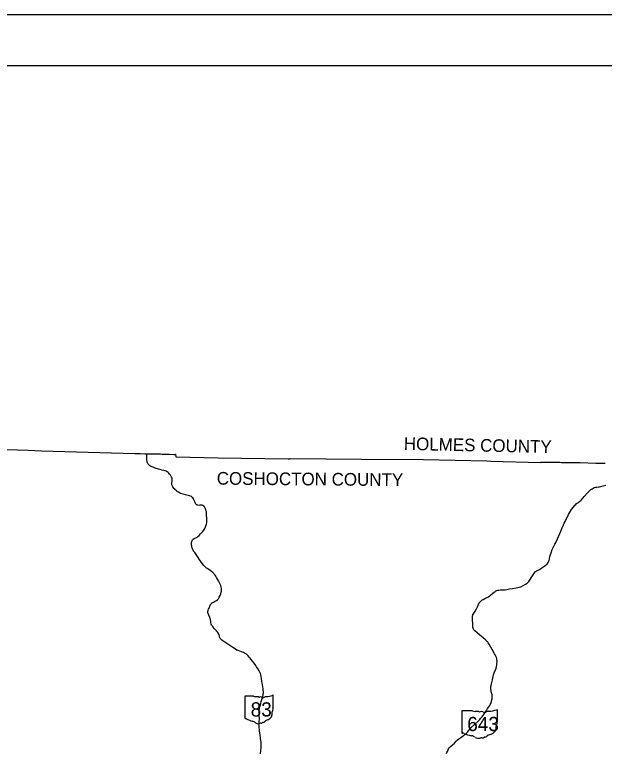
# Model space of a CAD drawing. Extents: x 1913970 to 2276415, y 78841 to 927181.
# Drawn here: x 2124487 to 2170995, y 868928 to 927181 of the extents above; entities that cross this region are included whole.
import ezdxf

# ---------------------------------------------------------------- set-up
doc = ezdxf.new("R2010")
doc.units = 0
for name, color, linetype in [('GM_X_County', 7, 'Continuous'), ('GM_X_County_Text', 7, 'Continuous'), ('GM_X_State_Location', 7, 'Continuous'), ('GM_X_State_Route', 7, 'Continuous'), ('GM_X_State_Shield', 7, 'Continuous'), ('SH_Border', 7, 'Continuous'), ('SH_Cut_Line', 7, 'Continuous')]:
    doc.layers.add(name, color=color, linetype=linetype)

msp = doc.modelspace()

# ---------------------------------------------------------------- linework, layer by layer
at = {"layer": 'GM_X_County'}
msp.add_lwpolyline([(2122132, 892938), (2125547, 892838), (2126585, 892786), (2133951, 892571), (2133956, 892572), (2133965, 892574), (2133971, 892575), (2133978, 892576), (2133984, 892576), (2133992, 892577), (2134003, 892576), (2134090, 892576), (2134158, 892574), (2134373, 892570), (2134751, 892558), (2134916, 892555), (2134951, 892554), (2135202, 892549), (2135323, 892546), (2135463, 892544), (2135510, 892543), (2135606, 892542), (2135654, 892541), (2135717, 892540), (2135760, 892539), (2135871, 892537), (2135937, 892535), (2135985, 892533), (2136113, 892530), (2136193, 892528), (2136275, 892528), (2136373, 892525), (2136668, 892518), (2137044, 892505), (2137101, 892504), (2137123, 892504), (2137135, 892506), (2137144, 892509), (2137152, 892512), (2137161, 892516), (2137167, 892519), (2137174, 892523), (2137184, 892297), (2140547, 892239), (2146047, 892160), (2146063, 892162), (2146077, 892162), (2146095, 892162), (2146113, 892162), (2146146, 892162), (2146163, 892162), (2146180, 892164), (2146195, 892168), (2146209, 892175), (2146221, 892185), (2151850, 892125), (2156726, 892101), (2161727, 891984), (2162058, 891979), (2165965, 891868), (2165997, 891878), (2166018, 891883), (2166043, 891888), (2166067, 891892), (2166116, 891896), (2166182, 891899), (2166281, 891898), (2166412, 891894), (2166494, 891893), (2166559, 891892), (2166608, 891891), (2166756, 891890), (2166870, 891888), (2167215, 891884), (2167358, 891882), (2167482, 891879), (2167618, 891874), (2167748, 891869), (2167839, 891866), (2167904, 891865), (2167986, 891863), (2168100, 891861), (2168214, 891860), (2168312, 891860), (2168426, 891859), (2168541, 891856), (2168639, 891854), (2168731, 891853), (2168881, 891856), (2168988, 891856), (2169036, 891855), (2169071, 891854), (2169103, 891852), (2170323, 891808), (2170390, 891809), (2170495, 891808), (2170634, 891807), (2170759, 891805), (2170942, 891804), (2171061, 891801)], dxfattribs=at)
at = {"layer": 'GM_X_State_Route'}
for points in [[(2135060, 891687), (2135025, 891726), (2134988, 891781), (2134959, 891835), (2134935, 891900), (2134921, 891955), (2134913, 892010), (2134907, 892062), (2134907, 892122), (2134907, 892258), (2134917, 892552)], [(2137112, 889749), (2137048, 889817), (2136962, 889938), (2136910, 890035), (2136885, 890113), (2136880, 890160), (2136880, 890201), (2136885, 890253), (2136908, 890374), (2136917, 890448), (2136917, 890508), (2136912, 890565), (2136894, 890628), (2136864, 890701), (2136767, 890854), (2136707, 890940), (2136649, 891018), (2136587, 891080), (2136510, 891138), (2136444, 891172), (2136358, 891202), (2136250, 891231), (2136079, 891269), (2135947, 891304), (2135825, 891341), (2135577, 891424), (2135411, 891481), (2135260, 891546), (2135187, 891583), (2135127, 891624), (2135063, 891683), (2135060, 891687)], [(2139730, 880073), (2139731, 880119), (2139737, 880178), (2139753, 880240), (2139775, 880305), (2139812, 880383), (2139876, 880523), (2139943, 880653), (2140003, 880735), (2140047, 880781), (2140104, 880823), (2140163, 880855), (2140246, 880895), (2140348, 880944), (2140409, 880980), (2140473, 881026), (2140521, 881073), (2140555, 881119), (2140592, 881172), (2140625, 881239), (2140688, 881382), (2140736, 881504), (2140782, 881635), (2140800, 881713), (2140808, 881785), (2140808, 881862), (2140807, 881931), (2140782, 882032), (2140736, 882153), (2140549, 882520), (2140407, 882797), (2140356, 882893), (2140295, 882984), (2140230, 883066), (2140187, 883114), (2140113, 883184), (2140042, 883240), (2139879, 883358), (2139666, 883500), (2139623, 883533), (2139582, 883565), (2139532, 883607), (2139474, 883663), (2139411, 883736), (2139311, 883869), (2139048, 884243), (2138963, 884364), (2138842, 884531), (2138685, 884752), (2138600, 884874), (2138550, 884957), (2138512, 885047), (2138484, 885126), (2138465, 885185), (2138451, 885256), (2138439, 885339), (2138433, 885389), (2138434, 885484), (2138442, 885556), (2138458, 885634), (2138491, 885710), (2138514, 885752), (2138565, 885814), (2138633, 885861), (2138684, 885889), (2138768, 885929), (2138866, 885980), (2138942, 886033), (2139036, 886111), (2139151, 886224), (2139292, 886392), (2139394, 886527), (2139481, 886663), (2139540, 886784), (2139573, 886869), (2139609, 886988), (2139631, 887097), (2139641, 887204), (2139637, 887417), (2139624, 887752), (2139616, 887879), (2139605, 887962), (2139593, 888035), (2139571, 888117), (2139540, 888200), (2139491, 888306), (2139455, 888358), (2139402, 888415), (2139335, 888460), (2139267, 888487), (2139195, 888499), (2139079, 888488), (2138998, 888482), (2138941, 888488), (2138889, 888505), (2138830, 888541), (2138782, 888585), (2138751, 888634), (2138713, 888715), (2138627, 888909), (2138581, 889003), (2138529, 889078), (2138470, 889138), (2138420, 889176), (2138362, 889209), (2138264, 889242), (2137958, 889312), (2137786, 889352), (2137674, 889382), (2137568, 889425), (2137485, 889466), (2137396, 889515), (2137299, 889580), (2137243, 889626), (2137126, 889734), (2137112, 889749)], [(2161274, 880947), (2161348, 881004), (2161451, 881066), (2161577, 881135), (2161728, 881207), (2161806, 881244), (2161867, 881278), (2161961, 881342), (2162085, 881440), (2162310, 881640), (2162380, 881693), (2162446, 881736), (2162518, 881768), (2162588, 881789), (2162677, 881802), (2162816, 881806), (2163034, 881810), (2163184, 881824), (2163310, 881842), (2163533, 881884), (2163751, 881918), (2164037, 881965), (2164170, 881989), (2164291, 882017), (2164416, 882065), (2164595, 882153), (2164784, 882254), (2164922, 882352), (2165003, 882423), (2165046, 882473), (2165108, 882565), (2165150, 882642), (2165233, 882774), (2165383, 882998), (2165488, 883171), (2165537, 883233), (2165579, 883268), (2165643, 883307), (2165740, 883354), (2165878, 883421), (2165993, 883491), (2166317, 883721), (2166486, 883857), (2166529, 883900), (2166574, 883967), (2166608, 884036), (2166637, 884131), (2166681, 884295), (2166712, 884436), (2166754, 884595), (2166799, 884749), (2166879, 884993), (2166927, 885106), (2167009, 885253), (2167103, 885424), (2167171, 885560), (2167297, 885851), (2167564, 886454), (2167651, 886658), (2167775, 886936), (2167845, 887088), (2167903, 887200), (2168020, 887446), (2168116, 887635), (2168185, 887762), (2168334, 888015), (2168424, 888144), (2168565, 888329), (2168688, 888490), (2168747, 888560), (2168808, 888617), (2168903, 888691), (2169064, 888814), (2169136, 888875), (2169199, 888930), (2169418, 889182), (2169666, 889459), (2169822, 889619), (2169936, 889721), (2170033, 889795), (2170119, 889843), (2170208, 889880), (2170318, 889911), (2170419, 889927), (2170544, 889938), (2170629, 889948), (2170728, 889967), (2170922, 890017), (2171133, 890080)], [(2160670, 878716), (2160647, 878784), (2160635, 878867), (2160623, 879137), (2160617, 879246), (2160611, 879356), (2160593, 879608), (2160591, 879701), (2160599, 879755), (2160615, 879810), (2160639, 879858), (2160801, 880123), (2160904, 880306), (2160992, 880481), (2161135, 880785), (2161173, 880846), (2161225, 880901), (2161274, 880947)], [(2143863, 868887), (2143891, 869153), (2143915, 869359), (2143927, 869527), (2143936, 869699), (2143929, 869820), (2143913, 869931), (2143884, 870108), (2143837, 870385), (2143796, 870658), (2143783, 870799), (2143778, 870948), (2143781, 871392), (2143783, 871634), (2143778, 871884), (2143770, 872085), (2143764, 872213), (2143766, 872286), (2143772, 872369), (2143791, 872466), (2143808, 872533), (2143846, 872668), (2143896, 872851), (2143938, 873006), (2144046, 873400), (2144075, 873534), (2144091, 873612), (2144100, 873695), (2144103, 873771), (2144096, 873896), (2144082, 874018), (2144032, 874320), (2144006, 874469), (2143990, 874579), (2143949, 874831), (2143925, 874976), (2143898, 875109), (2143865, 875222), (2143827, 875310), (2143769, 875423), (2143684, 875560), (2143564, 875750), (2143501, 875849), (2143383, 876025), (2143241, 876203), (2143119, 876355), (2143071, 876418), (2142992, 876514), (2142912, 876607), (2142849, 876666), (2142762, 876736), (2142666, 876800), (2142604, 876833), (2142526, 876870), (2142383, 876924), (2142233, 876975), (2142101, 877024), (2142016, 877064), (2141903, 877130), (2141692, 877270), (2141452, 877433), (2140977, 877748), (2140837, 877843), (2140765, 877900), (2140724, 877946), (2140705, 877974), (2140675, 878033), (2140653, 878105), (2140637, 878179), (2140615, 878243), (2140578, 878332), (2140507, 878446), (2140240, 878753), (2140162, 878842), (2140102, 878914), (2140057, 878978), (2140024, 879032), (2139986, 879120), (2139962, 879205), (2139945, 879304), (2139918, 879484), (2139906, 879561), (2139884, 879639), (2139802, 879828), (2139754, 879940), (2139732, 880014), (2139730, 880073)], [(2161015, 871441), (2161152, 871575), (2161270, 871696), (2161361, 871802), (2161425, 871886), (2161495, 871987), (2161548, 872065), (2161689, 872295), (2161719, 872342), (2161795, 872452), (2161882, 872580), (2161963, 872702), (2162008, 872779), (2162042, 872851), (2162096, 873001), (2162132, 873138), (2162149, 873224), (2162159, 873321), (2162160, 873398), (2162153, 873460), (2162140, 873536), (2162122, 873612), (2162084, 873780), (2162064, 873881), (2162050, 873999), (2162050, 874103), (2162054, 874184), (2162067, 874262), (2162100, 874407), (2162169, 874707), (2162228, 874991), (2162250, 875100), (2162276, 875193), (2162303, 875269), (2162331, 875337), (2162378, 875429), (2162433, 875551), (2162463, 875649), (2162490, 875781), (2162512, 875894), (2162528, 876011), (2162539, 876129), (2162538, 876204), (2162531, 876297), (2162512, 876386), (2162485, 876471), (2162440, 876587), (2162395, 876682), (2162343, 876777), (2162154, 877107), (2162044, 877303), (2161913, 877524), (2161833, 877646), (2161805, 877686), (2161744, 877762), (2161657, 877845), (2161445, 878027), (2161183, 878240), (2160963, 878423), (2160783, 878574), (2160729, 878627), (2160697, 878664), (2160670, 878716)], [(2158544, 868918), (2158584, 868980), (2158621, 869055), (2158675, 869186), (2158714, 869272), (2158773, 869357), (2158831, 869423), (2159171, 869727), (2159314, 869872), (2159424, 869985), (2159513, 870060), (2159668, 870166), (2159898, 870314), (2160033, 870421), (2160119, 870500), (2160209, 870601), (2160334, 870762), (2160385, 870823), (2160503, 870950), (2160751, 871196), (2161015, 871441)]]:
    msp.add_lwpolyline(points, dxfattribs=at)
at = {"layer": 'GM_X_State_Shield'}
for p, q in [((2142641, 873406), (2142641, 871705)), ((2143319, 873435), (2142663, 873435)), ((2144882, 872588), (2144882, 873478)), ((2144882, 872588), (2144882, 872588)), ((2159765, 872254), (2159765, 870553)), ((2160613, 872283), (2159793, 872283)), ((2162567, 871436), (2162567, 872326)), ((2162567, 871436), (2162567, 871436))]:
    msp.add_line(p, q, dxfattribs=at)
for centre, radius, start, end in [((2142666, 873410), 26, 98.1301, 188.1301), ((2143476, 873633), 252, 231.61951, 271.11188), ((2143559, 872480), 904, 80.48669, 94.98827), ((2143764, 873419), 72.7, 219.79206, 297.10237), ((2143871, 873222), 151, 54.46668, 119.14113), ((2144066, 873492), 182, 233.85621, 294.82819), ((2144387, 872916), 478, 97.34618, 120.76885), ((2144084, 875755), 2377, 275.84447, 288.90645), ((2144857, 873481), 25, 351.86209, 97.738), ((2144217, 872102), 595, 292.30889, 8.98584), ((2144972, 872215), 169, 136.8065, 186.92959), ((2144876, 872522), 38.6, 107.94398, 210.33697), ((2144631, 872410), 232, 340.03296, 23.64957), ((2144856, 872584), 26.7, 289.60381, 7.73413), ((2142667, 871701), 26.2, 171.95839, 258.30661), ((2142671, 871875), 200, 267.33899, 280.60386), ((2142712, 871607), 72.1, 29.74838, 93.27175), ((2143622, 873135), 1716, 240.41292, 257.1985), ((2143110, 870941), 537, 47.18416, 75.83597), ((2144468, 871227), 326, 94.40312, 142.57675), ((2143691, 871598), 341, 230.70037, 286.29184), ((2143888, 871010), 280, 85.69512, 111.20995), ((2143913, 871471), 182, 268.77702, 315.54927), ((2144077, 871306), 51.1, 65.75173, 132.64842), ((2144055, 871540), 192, 282.87319, 323.27711)]:
    msp.add_arc(centre, radius, start, end, dxfattribs=at)
for centre, major_axis, start_param, end_param in [((2159797, 872258), (32.5, 0), 1.712693, 3.28349), ((2160809, 872481), (315, 0), 4.042523, 4.731795), ((2160913, 871328), (1130, 0), 1.404758, 1.657858), ((2161170, 872267), (90.8, 0), 3.836095, 5.185415), ((2161303, 872070), (189, 0), 0.950623, 2.079405), ((2161547, 872340), (227, 0), 4.081561, 5.145723), ((2161948, 871764), (598, 0), 1.699011, 2.107814), ((2161569, 874603), (2971, 0), 4.814394, 5.042369), ((2162536, 872329), (31.2, 0), 6.141152, 7.989035), ((2161735, 870950), (743, 0), 5.101752, 6.440018), ((2162679, 871063), (211, 0), 2.387724, 3.262537), ((2162560, 871370), (48.3, 0), 1.883978, 3.671073), ((2162253, 871258), (290, 0), 5.934695, 6.695948), ((2162534, 871432), (33.4, 0), 5.05454, 6.418171), ((2159798, 870549), (32.7, 0), 3.00124, 4.508301), ((2159802, 870723), (250, 0), 4.665946, 4.897461), ((2159854, 870455), (90.1, 0), 0.519207, 1.627899), ((2160991, 871983), (2146, 0), 4.195997, 4.488961), ((2160352, 869789), (671, 0), 0.823519, 1.323587), ((2162049, 870075), (407, 0), 1.647645, 2.488434), ((2161078, 870446), (426, 0), 4.026481, 4.996735), ((2161324, 869858), (350, 0), 1.495662, 1.94098), ((2161355, 870319), (227, 0), 4.691044, 5.507374), ((2161560, 870154), (63.9, 0), 1.147584, 2.315152), ((2161533, 870388), (240, 0), 4.937069, 5.64225)]:
    msp.add_ellipse(centre, major_axis=major_axis, ratio=0.8, start_param=start_param, end_param=end_param, dxfattribs=at)
at = {"layer": 'SH_Border'}
msp.add_lwpolyline([(2016415, 923181), (2272415, 923181), (2272415, 755181), (2016415, 755181)], close=True, dxfattribs=at)
at = {"layer": 'SH_Cut_Line'}
msp.add_lwpolyline([(2004415, 751181), (2276415, 751181), (2276415, 927181), (2004415, 927181)], close=True, dxfattribs=at)

# ---------------------------------------------------------------- texts
at = {"layer": 'GM_X_County_Text'}
for s, rotation, p in [('HOLMES COUNTY', 358.73285, (2155175, 892858)), ('COSHOCTON COUNTY', 359.54831, (2140421, 890117))]:
    msp.add_text(s, height=1000, rotation=rotation, dxfattribs=at).set_placement(p)
at = {"layer": 'GM_X_State_Location'}
msp.add_text('643', height=1, rotation=0.00001, dxfattribs=at).set_placement((2162081, 876821))
for s in ['s', 'r']:
    msp.add_text(s, height=1, dxfattribs=at).set_placement((2162434, 876894))
at = {"layer": 'GM_X_State_Shield'}
for s, p in [('83', (2143097, 871825)), ('643', (2160186, 870673))]:
    msp.add_text(s, height=1120.7, dxfattribs=at).set_placement(p)

doc.saveas('drawing.dxf')
